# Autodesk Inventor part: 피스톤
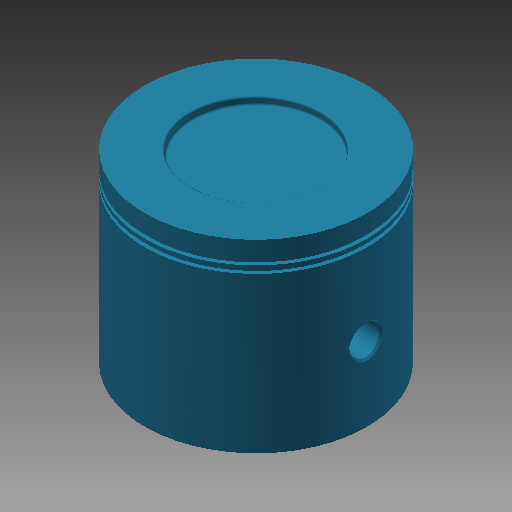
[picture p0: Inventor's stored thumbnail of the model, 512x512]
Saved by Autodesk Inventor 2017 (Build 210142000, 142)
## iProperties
Created: 2016-11
Part Number: 피스톤
Material: 강철, 탄소
Document SubType Name: Modeling
Designer: mduedu
Density: 7.87 g/cm^3
Mass: 410.115 g
Surface Area: 237.491 cm^2
Volume: 52.1112 cm^3
Appearance: 터키옥색
Author: mduedu
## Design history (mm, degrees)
sketch "스케치1"
  geometry: C1 r 30 at (0, 0); 1 further point
  constraints: 1 centre point, 1 coincident
  dimensions: "d0" = 60 diameter of C1
extrude "돌출1" new body sketch "스케치1" distance "d1" = 50; taper "d2" = 0 deg
sketch "스케치2"
  geometry: C1 r 28 at (0, 0); 1 further point
  constraints: 1 centre point, 1 coincident
  dimensions: "d3" = 56 diameter of C1
extrude "돌출2" cut sketch "스케치2" distance "d4" = 45; taper "d5" = 0 deg
sketch "스케치3"
  geometry: L1 (30, 0)-(30, 50) reference; L2 (30, 45)-(29, 45); L3 (29, 45)-(29, 44); L4 (29, 44)-(30, 44); L5 (30, 44)-(30, 45); L6 (30, 43)-(29, 43); L7 (29, 43)-(29, 42); L8 (29, 42)-(30, 42); L9 (30, 42)-(30, 43); L10 (30, 50)-(-30, 50) reference; L11 (0, 50)-(0, 0)
  constraints: 18 end point, 4 parallel, 3 equal length, 3 perpendicular, 2 horizontal, 2 point on line, 1 midpoint
  dimensions: "d6" = 1 distance of L2.start L2.end; "d8" = 5 distance between parallel lines of L10 L2; "d9" = 1 distance between parallel lines of L6 L4
revolve "회전1" sketch "스케치3" stored, may be unused: angle "d10" = 90 deg
node "작업 평면1"
sketch "스케치4"
  geometry: L1 (0, -22.978)-(45, -22.978) reference; L2 (45, -22.978)-(45, 22.978) reference; L3 (45, 22.978)-(0, 22.978) reference; L4 (0, 22.978)-(0, 25.377) reference; L5 (0, 25.377)-(42, 25.377) reference; L6 (42, 25.377)-(42, 24.187) reference; L7 (42, 24.187)-(43, 24.187) reference; L8 (43, 24.187)-(43, 25.377) reference; L9 (43, 25.377)-(44, 25.377) reference; L10 (44, 25.377)-(44, 24.187) reference; L11 (44, 24.187)-(45, 24.187) reference; L12 (45, 24.187)-(45, 25.377) reference; L13 (45, 25.377)-(50, 25.377) reference; L14 (50, 25.377)-(50, -25.377) reference; L15 (50, -25.377)-(45, -25.377) reference; L16 (45, -25.377)-(45, -24.187) reference; L17 (45, -24.187)-(44, -24.187) reference; L18 (44, -24.187)-(44, -25.377) reference; L19 (44, -25.377)-(43, -25.377) reference; L20 (43, -25.377)-(43, -24.187) reference; L21 (43, -24.187)-(42, -24.187) reference; L22 (42, -24.187)-(42, -25.377) reference; L23 (42, -25.377)-(0, -25.377) reference; L24 (0, -25.377)-(0, -22.978) reference; L25 (12.5, 22.978)-(45, 22.978); L26 (45, 22.978)-(45, -22.978); L27 (45, -22.978)-(12.5, -22.978); L28 (12.5, -22.978)-(12.5, 22.978); C1 r 7.5 at (20, 0); C2 r 4 at (20, 0); 1 further point
  constraints: 8 end point, 2 centre point, 2 parallel, 1 coincident, 1 horizontal, 1 horizontal alignment, 1 perpendicular, 1 point on line, 1 tangent
  dimensions: "d12" = 15 diameter of C1; "d13" = 8 diameter of C2; "d14" = 20 distance of point (0, 0) C1.centre
  node "절단 모서리 투영1"
extrude "돌출3" join sketch "스케치4" stored distance "d15" = 11.75; taper "d16" = 0 deg
extrude "돌출4" cut sketch "스케치4" stored distance "d17" = 72; taper "d18" = 0 deg
fillet "모깎기2" dims "d20" = 3
chamfer "모따기1" distance "d21" = 0.5; stored, may be unused: second distance "d22" = 2, angle "d23" = 45 deg
chamfer "모따기2" distance "d24" = 0.5; stored, may be unused: second distance "d25" = 2, angle "d26" = 45 deg
sketch "스케치5"
  geometry: C1 r 17.5 at (0, 0); 1 further point
  constraints: 1 centre point, 1 coincident
  dimensions: "d27" = 35 diameter of C1
extrude "돌출5" cut sketch "스케치5" distance "d28" = 2; taper "d29" = 0 deg
fillet "모깎기3" dims "d30" = 0.5
node "솔리드1"
mirror "대칭1"
other parameters: "d11" = -16
